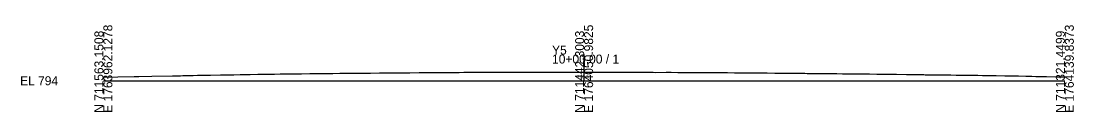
# Model space of a CAD drawing. Extents: x -26 to 303, y -10 to 4039.
# Drawn here: x -25.7 to 302.8, y -9.7 to 17.3 of the extents above; entities that cross this region are included whole.
import ezdxf

# ---------------------------------------------------------------- set-up
doc = ezdxf.new("R2010")
doc.units = 0
for name, color, linetype in [('Default', 7, 'Continuous'), ('Exist Cross Section Cell', 7, 'Continuous'), ('Exist XS Center Line Elevation Label', 7, 'Continuous'), ('Exist XS Ground Line', 7, 'Continuous')]:
    doc.layers.add(name, color=color, linetype=linetype)

msp = doc.modelspace()

# ---------------------------------------------------------------- linework, layer by layer
at = {"layer": 'Exist Cross Section Cell'}
for p, q in [((150, 0), (150, 8.16)), ((0, 0), (150, 0)), ((150, 0), (300, 0))]:
    msp.add_line(p, q, dxfattribs=at)
at = {"layer": 'Exist XS Ground Line'}
msp.add_lwpolyline([(0, 1.1), (4.52, 1.2), (9.56, 1.3), (10.27, 1.31), (11.04, 1.33), (15.16, 1.42), (21.54, 1.55), (22.32, 1.56), (24.08, 1.57), (24.75, 1.59), (27.18, 1.66), (28.06, 1.68), (29.34, 1.69), (30.29, 1.71), (32.28, 1.75), (33.39, 1.78), (36.5, 1.83), (39.6, 1.87), (40.72, 1.89), (42.7, 1.93), (44.94, 1.97), (45.8, 1.99), (48.19, 2.03), (49.16, 2.04), (52.01, 2.07), (53.38, 2.09), (55.11, 2.11), (57.6, 2.14), (58.21, 2.14), (59.91, 2.17), (61.32, 2.19), (61.82, 2.19), (64.42, 2.22), (66.04, 2.23), (67.52, 2.25), (70.26, 2.28), (70.63, 2.28), (71.63, 2.29), (73.73, 2.32), (74.48, 2.32), (76.83, 2.35), (78.71, 2.36), (79.93, 2.37), (83.04, 2.41), (83.35, 2.41), (86.14, 2.44), (87.15, 2.45), (89.24, 2.47), (91.37, 2.49), (92.35, 2.5), (95.07, 2.5), (95.59, 2.5), (98.55, 2.53), (99.81, 2.54), (101.66, 2.55), (104.03, 2.57), (104.76, 2.58), (106.79, 2.59), (107.86, 2.59), (108.25, 2.59), (110.96, 2.62), (112.47, 2.63), (114.07, 2.64), (116.69, 2.66), (117.17, 2.66), (118.51, 2.67), (120.27, 2.68), (120.91, 2.68), (121.84, 2.69), (124.27, 2.7), (126.69, 2.7), (127.99, 2.7), (129.37, 2.72), (130.23, 2.72), (132.69, 2.71), (133.57, 2.71), (135.45, 2.72), (138.55, 2.71), (142.01, 2.72), (145.1, 2.72), (146.23, 2.71), (150, 2.7), (151.64, 2.7), (152.54, 2.7), (153.67, 2.71), (154.67, 2.71), (157.51, 2.69), (158.1, 2.69), (158.89, 2.68), (159.27, 2.67), (162.58, 2.68), (165.39, 2.67), (166.82, 2.67), (167.33, 2.67), (169.92, 2.65), (171.55, 2.63), (172.25, 2.62), (175.59, 2.64), (177.11, 2.63), (179.23, 2.61), (179.99, 2.61), (182.33, 2.6), (184.21, 2.59), (185.32, 2.58), (188.44, 2.56), (188.83, 2.56), (191.64, 2.54), (192.66, 2.53), (194.75, 2.52), (196.88, 2.5), (200.55, 2.49), (201.1, 2.49), (204.05, 2.46), (205.32, 2.46), (207.16, 2.43), (209.54, 2.4), (210.75, 2.39), (212.27, 2.38), (213.76, 2.37), (215.43, 2.35), (216.47, 2.35), (217.98, 2.33), (218.9, 2.32), (219.57, 2.31), (222.2, 2.28), (222.67, 2.27), (223.99, 2.26), (226.05, 2.24), (226.42, 2.24), (228.88, 2.21), (230.64, 2.19), (231.98, 2.17), (235.08, 2.15), (235.71, 2.15), (238.19, 2.12), (239.08, 2.11), (241.29, 2.08), (242.14, 2.07), (243.3, 2.07), (244.39, 2.06), (247.52, 2.01), (250.6, 1.96), (251.74, 1.95), (253.7, 1.93), (255.96, 1.9), (256.45, 1.89), (256.81, 1.89), (259.15, 1.87), (260.18, 1.86), (263.01, 1.82), (263.6, 1.81), (264.4, 1.81), (266.11, 1.79), (268.62, 1.75), (269.22, 1.74), (270.75, 1.73), (272.54, 1.7), (272.84, 1.69), (274.33, 1.67), (275.42, 1.64), (277.06, 1.62), (278.53, 1.6), (281.28, 1.56), (281.63, 1.55), (283.27, 1.53), (284.73, 1.51), (285.5, 1.49), (287.84, 1.44), (288.64, 1.43), (289.72, 1.4), (290.94, 1.37), (294.31, 1.32), (297.15, 1.26), (297.58, 1.25), (298.16, 1.24), (299.37, 1.21), (300, 1.2)], dxfattribs=at)

# ---------------------------------------------------------------- texts
at = {"layer": 'Default'}
msp.add_text('-', height=0.0001, dxfattribs=at).set_placement((0, 0))
at = {"layer": 'Exist Cross Section Cell'}
for s, p in [('E 1763962.1278', (2.8, -10)), ('E 1764050.9825', (152.8, -10)), ('E 1764139.8373', (302.8, -10)), ('N 711563.1508', (0, -10)), ('N 711442.3003', (150, -10)), ('N 711321.4499', (300, -10))]:
    msp.add_text(s, height=2.8, rotation=90, dxfattribs=at).set_placement(p)
for s, p in [('Y5', (140, 8.16)), ('10+00.00 / 1', (140, 5.36)), ('EL 794', (-26, -1.4))]:
    msp.add_text(s, height=2.8, dxfattribs=at).set_placement(p)
at = {"layer": 'Exist XS Center Line Elevation Label'}
msp.add_text('796.70', height=1, dxfattribs=at).set_placement((147.85, 0.7))

doc.saveas('drawing.dxf')
